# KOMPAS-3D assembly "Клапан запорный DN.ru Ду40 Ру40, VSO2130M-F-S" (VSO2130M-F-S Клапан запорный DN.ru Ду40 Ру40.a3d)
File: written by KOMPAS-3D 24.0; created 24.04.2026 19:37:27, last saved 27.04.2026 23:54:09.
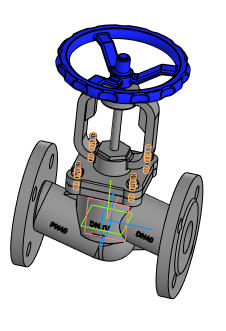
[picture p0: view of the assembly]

Document properties: Автор: DN.ru; Полное имя файла: C:\Работа\ГОТОВЫЕ ИСХОДНИКИ\VSO2130M-F-S Клапан запорный сальниковый DN.ru Ду15-100 Ру40\исходные материалы\DN40\VSO2130M-F-S Клапан запорный DN.ru Ду40 Ру40.a3d

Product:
- Component [detail]: Корпус  | qty 1  | pos. 1  | Масса: 6.9; Автор: R2D2; source file: Korpus.m3d
- Component [detail]: Деталь  | qty 1  | pos. 2  | Масса: 1.566924; Автор: mrdid; source file: rama.m3d
- Component [detail]: Деталь2  | qty 1  | pos. 3  | Масса: 0.882711; Автор: R2D2; additional columns: Типовые; source file: shturval.m3d
- Component [standard]: Шпилька М8-6gx30 ГОСТ 22032-76  | qty 4  | Масса: 0.01271; Раздел спецификации: Стандартные изделия; Рассекать на разрезах: no
- Component [standard]: Гайка М8-6H ГОСТ 5915-70  | qty 4  | Масса: 0.005548; Раздел спецификации: Стандартные изделия; Рассекать на разрезах: no
- Part/product: Клапан запорный DN.ru Ду40 Ру40  | designation VSO2130M-F-S
    Масса: 13.5
    Раздел спецификации: Прочие изделия
    Примечание: D090-01983

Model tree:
1. Контекстная связь:1  (with: Контекстная связь (Деталь):1)  (labels: Грань.Твердое тело1)
2. Контекстная связь:2  (with: Смещенная плоскость:4, Контекстная связь (Деталь):2)  (labels: Грань.Твердое тело1)
3. Контекстная связь:3  (with: Контекстная связь (Корпус):3)
4. Контекстная связь:4  (with: Эскиз:2, Ребро.Элемент выдавливания:14, Контекстная связь (Деталь):4)
5. Контекстная связь:5  (with: Контекстная связь (Деталь):5)
6. Массив по концентрической сетке:1  (with: Грань.Элемент выдавливания:1, Грань.Элемент выдавливания:15, Грань.Элемент выдавливания:3, Грань.Элемент выдавливания:2, Грань.Элемент выдавливания:16, Грань.Элемент выдавливания:14)  (labels: Грань.Твердое тело1)  (4 pattern instances)
     Шаг 2 = 360; Угол = 9

Referenced files in C:\Работа\ГОТОВЫЕ ИСХОДНИКИ\VSO2130M-F-S Клапан запорный сальниковый DN.ru Ду15-100 Ру40\исходные материалы\DN40\: Korpus.m3d, rama.m3d, shturval.m3d
Referenced files in C:\Program Files\ASCON\KOMPAS-3D v24\Libs\PolynomLib\DATA\vault\Methods\Kompas\3D\: PLib_Stud_1_900.m3d, PLib_Nut_OST92_900.m3d
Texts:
  BOSimple***PART:059b53d5-85de-be37-d9a2-ab7837626634***SHORTLOC:Root±30±20±10±120±10±20[Нет;Без покрытия;Без указания материала;-;8;30;1,25;1,25]
  BOSimple***PART:bd0d297a-feeb-be2b-2a2a-05cd1c87d412***SHORTLOC:Root±30±10±20±©{}110±10±50±60[Нет;Без покрытия;Без указания материала;-;8;1,25;13]
  Программные изделия  и базы данных
  Крепежное изделие ГОСТ
  VSO2130M-F-S
  Деталь2 Деталь2
  Шпилька М8-6gx30 ГОСТ 22032-76 (1)
  cut1
  Гайка М8-6H ГОСТ 5915-70 (1)
  bcut1
  hole1
  hcut1
  hole2
  Шпилька М8-6gx30 ГОСТ 22032-76 (2)
  Гайка М8-6H ГОСТ 5915-70 (2)
  Шпилька М8-6gx30 ГОСТ 22032-76 (3)
  Гайка М8-6H ГОСТ 5915-70 (3)
  Шпилька М8-6gx30 ГОСТ 22032-76 (4)
  Гайка М8-6H ГОСТ 5915-70 (4)
  Плоскость ZX.Начало координат
  Плоскость XY.Начало координат
  Plane. Начало координат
